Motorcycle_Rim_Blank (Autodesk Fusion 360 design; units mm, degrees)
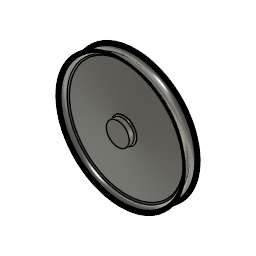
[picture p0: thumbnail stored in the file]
part number: 2026-08-31-11-11-36-547
sketch "Sketch1" plane through (0, 0, 0) normal (1, 0, 0) x axis (0, 1, 0)
  line L1 (43.3405, 0) -> (0, 0)
  line L2 (0, 215.9) -> (0, 0)
  line L3 (-13.3809, 215.9) -> (0, 215.9)
  line L4 (25.5408, 229.8483) -> (23.5384, 228.4766)
  line L5 (28.4122, 235.4523) -> (27.4891, 232.4871)
  line L6 (28.6382, 238.9535) -> (28.6382, 236.9385)
  line L7 (24.4105, 231.4983) -> (22.4081, 230.1266)
  line L8 (26.5026, 236.0468) -> (25.5795, 233.0816)
  line L9 (26.6382, 238.9535) -> (26.6382, 236.9385)
  line L10 (28.6382, 238.9535) -> (26.6382, 238.9535)
  line L11 (-25.5408, 229.8483) -> (-23.5384, 228.4766)
  line L12 (-28.4122, 235.4523) -> (-27.4891, 232.4871)
  line L13 (-28.6382, 238.9535) -> (-28.6382, 236.9385)
  line L14 (-28.6382, 238.9535) -> (-26.6382, 238.9535)
  line L15 (-26.6382, 238.9535) -> (-26.6382, 236.9385)
  line L16 (-26.5026, 236.0468) -> (-25.5795, 233.0816)
  line L17 (-24.4105, 231.4983) -> (-22.4081, 230.1266)
  line L18 (15, 42.5) -> (5, 216.3573)
  line L19 (38, 42.5) -> (15, 42.5)
  line L20 (38, 0) -> (38, 42.5)
  line L21 (-15, 42.5) -> (-5, 216.3573)
  line L22 (-38, 42.5) -> (-15, 42.5)
  line L23 (-38, 0) -> (-38, 42.5)
  line L24 (38, 0) -> (-38, 0)
  arc A1 centre (0, 243.4614) radius 27.5614 clockwise from (22.3157, 227.2861) to (0, 215.9)
  arc A2 centre (23.6382, 236.9385) radius 5 clockwise from (28.6382, 236.9385) to (28.4122, 235.4523)
  arc A3 centre (22.7151, 233.9733) radius 5 clockwise from (27.4891, 232.4871) to (25.5408, 229.8483)
  arc A4 centre (26.3641, 224.3517) radius 5 clockwise from (22.3157, 227.2861) to (23.5384, 228.4766)
  arc A5 centre (0, 243.4614) radius 25.5614 clockwise from (20.6964, 228.4598) to (0, 217.9)
  arc A6 centre (26.3641, 224.3517) radius 7 clockwise from (20.6964, 228.4598) to (22.4081, 230.1266)
  arc A7 centre (22.7151, 233.9733) radius 3 clockwise from (25.5795, 233.0816) to (24.4105, 231.4983)
  arc A8 centre (23.6382, 236.9385) radius 3 clockwise from (26.6382, 236.9385) to (26.5026, 236.0468)
  arc A9 centre (0, 243.4614) radius 27.5614 clockwise from (0, 215.9) to (-22.3157, 227.2861)
  arc A10 centre (-26.3641, 224.3517) radius 5 clockwise from (-23.5384, 228.4766) to (-22.3157, 227.2861)
  arc A11 centre (-22.7151, 233.9733) radius 5 clockwise from (-25.5408, 229.8483) to (-27.4891, 232.4871)
  arc A12 centre (-23.6382, 236.9385) radius 5 clockwise from (-28.4122, 235.4523) to (-28.6382, 236.9385)
  arc A13 centre (-23.6382, 236.9385) radius 3 clockwise from (-26.5026, 236.0468) to (-26.6382, 236.9385)
  arc A14 centre (-22.7151, 233.9733) radius 3 clockwise from (-24.4105, 231.4983) to (-25.5795, 233.0816)
  arc A15 centre (-26.3641, 224.3517) radius 7 clockwise from (-22.4081, 230.1266) to (-20.6964, 228.4598)
  arc A16 centre (0, 243.4614) radius 25.5614 clockwise from (0, 217.9) to (-20.6964, 228.4598)
  point P1 (0, 0)
  point P2 (0, 0)
  point P4 (0, 215.9)
  point P30 (0, 215.9)
  point P7 (28.6382, 238.9535)
  point P40 (-28.6382, 238.9535)
  point P8 (28.4122, 235.4523)
  point P37 (-28.4122, 235.4523)
  point P9 (28.6382, 236.9385)
  point P39 (-28.6382, 236.9385)
  point P11 (25.5408, 229.8483)
  point P34 (-25.5408, 229.8483)
  point P12 (27.4891, 232.4871)
  point P36 (-27.4891, 232.4871)
  point P14 (23.5384, 228.4766)
  point P33 (-23.5384, 228.4766)
  point P15 (22.3157, 227.2861)
  point P31 (-22.3157, 227.2861)
  point P18 (20.6964, 228.4598)
  point P50 (-20.6964, 228.4598)
  point P19 (0, 217.9)
  point P52 (0, 217.9)
  point P21 (22.4081, 230.1266)
  point P48 (-22.4081, 230.1266)
  point P22 (24.4105, 231.4983)
  point P47 (-24.4105, 231.4983)
  point P24 (25.5795, 233.0816)
  point P45 (-25.5795, 233.0816)
  point P25 (26.5026, 236.0468)
  point P44 (-26.5026, 236.0468)
  point P27 (26.6382, 236.9385)
  point P42 (-26.6382, 236.9385)
  point P28 (26.6382, 238.9535)
  point P41 (-26.6382, 238.9535)
  point P53 (5, 216.3573)
  point P56 (38, 0)
  point P57 (-5, 216.3573)
  point P54 (15, 42.5)
  point P58 (-15, 42.5)
  point P55 (38, 42.5)
  point P59 (-38, 42.5)
  point P60 (-38, 0)
  coincident P1 P2
  horizontal L1
  perpendicular L1 L2
  perpendicular L2 L3
  tangent L3 A1
  vertical L6
  tangent L5 A2
  tangent L6 A2
  tangent L4 A3
  tangent L5 A3
  equal A2 A3
  tangent A1 A4
  tangent L4 A4
  equal A2 A4
  perpendicular L6 L10
  symmetric P4 L2 P30
  symmetric L2 A1 A9
  symmetric L2 P7 P40
  symmetric L2 P8 P37
  symmetric L2 P9 P39
  symmetric L2 A2 A12
  symmetric L2 P11 P34
  symmetric L2 P12 P36
  symmetric L2 A3 A11
  symmetric L2 P14 P33
  symmetric L2 P15 P31
  symmetric L2 A4 A10
  symmetric L2 P18 P50
  symmetric L2 P19 P52
  symmetric L2 A5 A16
  symmetric L2 P21 P48
  symmetric L2 A6 A15
  symmetric L2 P22 P47
  symmetric L2 P24 P45
  symmetric L2 A7 A14
  symmetric L2 P25 P44
  symmetric L2 P27 P42
  symmetric L2 A8 A13
  symmetric L2 P28 P41
  coincident A1 P53
  horizontal L19
  coincident L1 P56
  perpendicular L1 L20
  symmetric L2 P53 P57
  symmetric L2 P54 P58
  symmetric L2 P55 P59
  symmetric L2 P56 P60
  dimension "d1" = 431.8
  dimension "d2" radius A2 = 5
  dimension "d3" = -2
  dimension "d4" = 85
  dimension "d5" distance L2 L20 = 38
  dimension "d6" distance L2 P54 = 15
  dimension "d7" distance L2 P53 = 5
revolve "Revolve1" sketch "Sketch1" AlongAngle 360
fillet "Fillet1" radius 5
